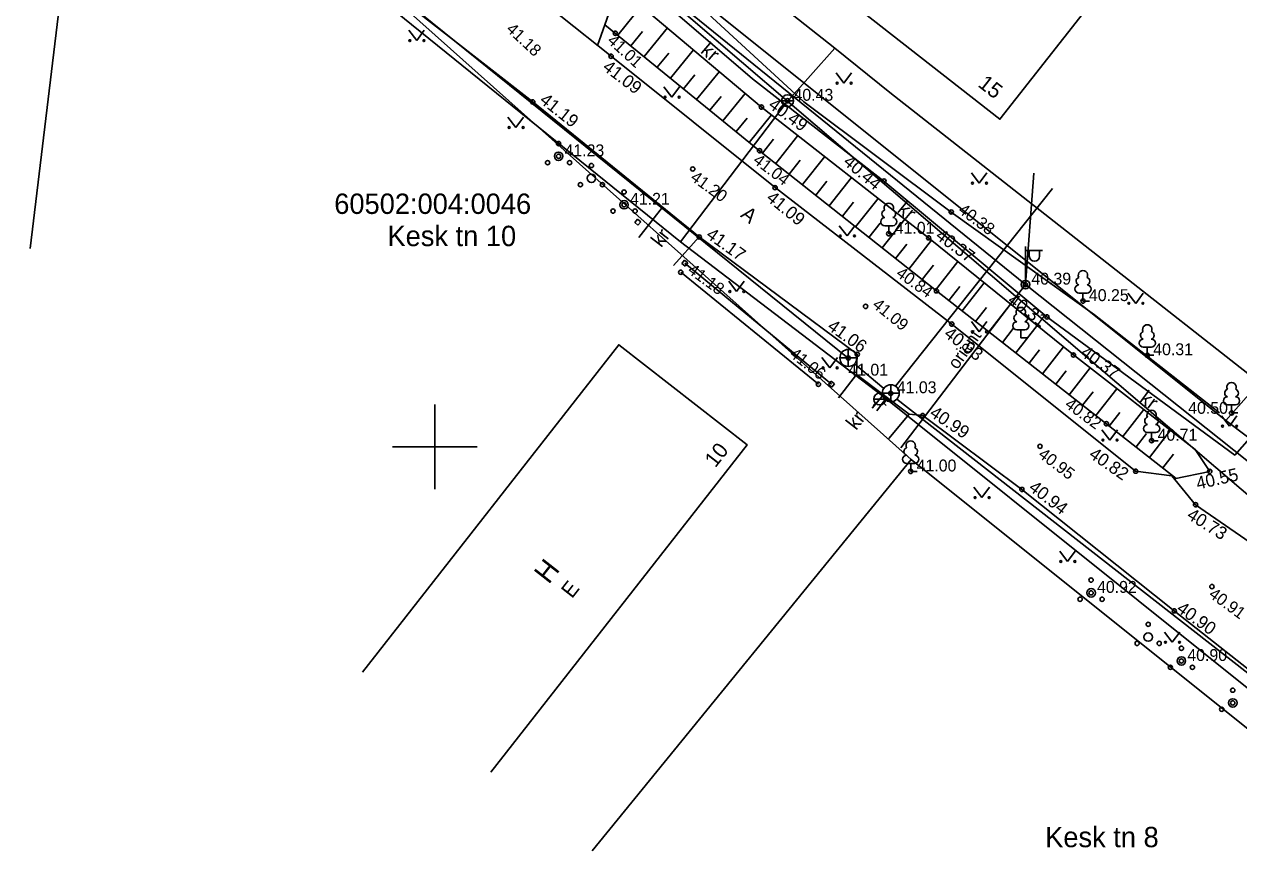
# Model space of a CAD drawing. Extents: x 641898 to 642452, y 6471715 to 6472255.
# Drawn here: x 642175.8 to 642247.4, y 6471876 to 6471924.9 of the extents above; entities that cross this region are included whole.
import ezdxf

# ---------------------------------------------------------------- set-up
doc = ezdxf.new("R2010")
doc.units = 0
for name, color, linetype in [('AED', 7, 'Continuous'), ('HALJASTUS', 7, 'Continuous'), ('HOONE', 7, 'Continuous'), ('KKAEV', 7, 'Continuous'), ('KORGUS-EH2000', 7, 'Continuous'), ('KTRASS', 7, 'Continuous'), ('MPOHULIIN', 7, 'Continuous'), ('PIIR', 7, 'Continuous'), ('POST', 7, 'Continuous'), ('PUU', 7, 'Continuous'), ('RELJEEF', 7, 'Continuous'), ('TEE', 7, 'Continuous'), ('VKAEV', 7, 'Continuous'), ('VORK', 7, 'Continuous'), ('VTRASS', 7, 'Continuous')]:
    doc.layers.add(name, color=color, linetype=linetype)

msp = doc.modelspace()

# ---------------------------------------------------------------- linework, layer by layer
at = {"layer": 'AED'}
for p, q in [((642211.941, 6471913.406), (642211.777, 6471913.218)), ((642211.777, 6471913.218), (642211.965, 6471913.054)), ((642211.941, 6471913.406), (642212.129, 6471913.242)), ((642212.129, 6471913.242), (642211.965, 6471913.054)), ((642214.702, 6471910.995), (642214.543, 6471910.802)), ((642214.543, 6471910.802), (642214.736, 6471910.643)), ((642214.702, 6471910.995), (642214.895, 6471910.836)), ((642214.719, 6471910.819), (642223.37, 6471903.693)), ((642214.895, 6471910.836), (642214.736, 6471910.643)), ((642223.194, 6471903.676), (642223.353, 6471903.869)), ((642223.546, 6471903.71), (642223.353, 6471903.869)), ((642223.387, 6471903.517), (642223.194, 6471903.676)), ((642223.387, 6471903.517), (642223.546, 6471903.71))]:
    msp.add_line(p, q, dxfattribs=at)
at = {"layer": 'HALJASTUS'}
for p, q in [((642198.464, 6471924.531), (642198.927, 6471923.924)), ((642198.927, 6471923.924), (642199.373, 6471924.531)), ((642223.635, 6471922.024), (642224.098, 6471921.417)), ((642224.098, 6471921.417), (642224.544, 6471922.024)), ((642213.497, 6471921.203), (642213.96, 6471920.596)), ((642213.96, 6471920.596), (642214.406, 6471921.203)), ((642204.307, 6471919.418), (642204.771, 6471918.811)), ((642204.771, 6471918.811), (642205.216, 6471919.418)), ((642231.607, 6471916.14), (642232.071, 6471915.533)), ((642232.071, 6471915.533), (642232.516, 6471916.14)), ((642223.826, 6471913.025), (642224.289, 6471912.419)), ((642224.289, 6471912.419), (642224.735, 6471913.025)), ((642217.316, 6471909.751), (642217.779, 6471909.145)), ((642217.779, 6471909.145), (642218.225, 6471909.751)), ((642240.828, 6471909.059), (642241.291, 6471908.452)), ((642241.291, 6471908.452), (642241.737, 6471909.059)), ((642231.607, 6471907.384), (642232.071, 6471906.777)), ((642232.071, 6471906.777), (642232.516, 6471907.384)), ((642222.807, 6471905.256), (642223.27, 6471904.649)), ((642223.27, 6471904.649), (642223.716, 6471905.256)), ((642246.348, 6471901.831), (642246.811, 6471901.224)), ((642246.811, 6471901.224), (642247.257, 6471901.831)), ((642239.301, 6471901.008), (642239.764, 6471900.402)), ((642239.764, 6471900.402), (642240.21, 6471901.008)), ((642231.763, 6471897.617), (642232.226, 6471897.01)), ((642232.226, 6471897.01), (642232.672, 6471897.617)), ((642236.814, 6471893.856), (642237.277, 6471893.249)), ((642237.277, 6471893.249), (642237.723, 6471893.856)), ((642242.98, 6471889.096), (642243.444, 6471888.489)), ((642243.444, 6471888.489), (642243.889, 6471889.096))]:
    msp.add_line(p, q, dxfattribs=at)
for points in [[(642212.922, 6471928.455), (642221.728, 6471920.311), (642230.423, 6471913.829), (642238.86, 6471907.776), (642246.219, 6471901.994)], [(642214.485, 6471910.283), (642222.598, 6471903.689)]]:
    msp.add_lwpolyline(points, dxfattribs=at)
for centre in [(642198.526, 6471923.924), (642199.355, 6471923.924), (642223.697, 6471921.417), (642224.526, 6471921.417), (642213.559, 6471920.596), (642214.388, 6471920.596), (642204.37, 6471918.811), (642205.198, 6471918.811), (642231.67, 6471915.533), (642232.498, 6471915.533), (642223.888, 6471912.419), (642224.717, 6471912.419), (642217.378, 6471909.145), (642218.207, 6471909.145), (642240.89, 6471908.452), (642241.719, 6471908.452), (642231.67, 6471906.777), (642232.498, 6471906.777), (642222.869, 6471904.649), (642223.698, 6471904.649), (642246.41, 6471901.224), (642247.239, 6471901.224), (642239.363, 6471900.402), (642240.192, 6471900.402), (642231.825, 6471897.01), (642232.654, 6471897.01), (642236.876, 6471893.249), (642237.705, 6471893.249), (642243.042, 6471888.489), (642243.871, 6471888.489)]:
    msp.add_circle(centre, 0.055, dxfattribs=at)
at = {"layer": 'HOONE'}
for points in [[(642240.821, 6471928.89), (642233.287, 6471919.295), (642217.105, 6471931.958), (642224.638, 6471941.553), (642240.821, 6471928.89)], [(642195.732, 6471886.734), (642210.829, 6471906.017), (642218.394, 6471900.125), (642203.303, 6471880.85)]]:
    msp.add_lwpolyline(points, dxfattribs=at)
at = {"layer": 'KKAEV'}
for p, q in [((642224.359, 6471904.734), (642224.359, 6471905.734)), ((642223.859, 6471905.234), (642224.859, 6471905.234)), ((642226.362, 6471903.159), (642227.362, 6471903.159)), ((642226.862, 6471902.659), (642226.862, 6471903.659))]:
    msp.add_line(p, q, dxfattribs=at)
for centre in [(642224.359, 6471905.234), (642226.862, 6471903.159)]:
    msp.add_circle(centre, 0.5, dxfattribs=at)
at = {"layer": 'KORGUS-EH2000'}
for centre in [(642210.631, 6471924.357), (642210.382, 6471923.001), (642205.766, 6471920.313), (642220.779, 6471920.383), (642219.24, 6471920.009), (642219.132, 6471917.438), (642207.287, 6471917.112), (642215.191, 6471916.365), (642220.045, 6471915.264), (642226.459, 6471915.651), (642211.146, 6471914.258), (642230.423, 6471913.829), (642215.573, 6471912.361), (642226.74, 6471912.55), (642229.091, 6471912.308), (642214.485, 6471910.283), (642234.793, 6471909.555), (642229.553, 6471909.186), (642225.374, 6471908.271), (642238.184, 6471908.585), (642236.062, 6471907.65), (642230.451, 6471907.231), (642224.359, 6471905.234), (642224.883, 6471905.449), (642237.623, 6471905.411), (642241.974, 6471905.397), (642222.598, 6471903.689), (642226.862, 6471903.159), (642228.739, 6471901.846), (642246.936, 6471901.997), (642239.564, 6471901.36), (642242.228, 6471900.362), (642235.652, 6471900.03), (642228.033, 6471898.552), (642241.287, 6471898.567), (642245.655, 6471898.552), (642234.582, 6471897.491), (642244.819, 6471896.591), (642245.779, 6471891.77), (642238.662, 6471891.402), (642243.566, 6471890.342), (642243.982, 6471887.389), (642247.009, 6471884.919)]:
    msp.add_circle(centre, 0.125, dxfattribs=at)
at = {"layer": 'KTRASS'}
for points in [[(642155.58, 6471980.633), (642150.419, 6471974.152), (642145.759, 6471968.585), (642185.052, 6471936.9), (642224.346, 6471905.214)], [(642227.137, 6471903.577), (642236.381, 6471915.22)], [(642226.446, 6471903.437), (642224.725, 6471904.893)], [(642226.032, 6471902.121), (642226.528, 6471902.787)], [(642255.424, 6471880.798), (642227.22, 6471902.81)]]:
    msp.add_lwpolyline(points, dxfattribs=at)
at = {"layer": 'MPOHULIIN'}
for points in [[(642355.522, 6471813.313), (642331.534, 6471832.393), (642302.222, 6471855.921), (642271.629, 6471880.301), (642234.793, 6471909.555), (642198.436, 6471939.015), (642169.975, 6471961.956), (642133.076, 6471995.171), (642102.99, 6472021.089), (642074.552, 6472045.947), (642044.597, 6472041.824), (642019.939, 6472060.923), (641980.015, 6472091.706), (641945.513, 6472065.466), (641932.178, 6472056.628)], [(642235.289, 6471916.123), (642234.793, 6471909.555)], [(642227.443, 6471899.938), (642234.793, 6471909.555)]]:
    msp.add_lwpolyline(points, dxfattribs=at)
at = {"layer": 'PIIR'}
for p, q in [((642246.6, 6471901.55), (642186.7, 6471949.52)), ((642186.7, 6471949.52), (642250.92, 6471894.58)), ((642176.155, 6471911.686), (642179.85, 6471942.23)), ((642179.85, 6471942.23), (642228.06, 6471899.25)), ((642262.52, 6471919.68), (642246.6, 6471901.55)), ((642246.6, 6471901.55), (642252.4, 6471897.15)), ((642209.264, 6471876.218), (642228.06, 6471899.25)), ((642228.06, 6471899.25), (642288.16, 6471851.19))]:
    msp.add_line(p, q, dxfattribs=at)
at = {"layer": 'POST'}
for p, q in [((642234.793, 6471909.805), (642234.793, 6471911.805)), ((642234.793, 6471911.555), (642235.793, 6471911.555)), ((642235.02, 6471911.234), (642235.02, 6471911.555)), ((642235.632, 6471911.234), (642235.632, 6471911.555))]:
    msp.add_line(p, q, dxfattribs=at)
msp.add_circle((642234.793, 6471909.555), 0.25, dxfattribs=at)
msp.add_arc((642235.326, 6471911.234), 0.306, 180, 0, dxfattribs=at)
at = {"layer": 'PUU'}
for p, q in [((642226.98, 6471913.025), (642226.5, 6471913.025)), ((642226.74, 6471912.55), (642226.74, 6471913.025)), ((642227.12, 6471912.55), (642226.74, 6471912.55)), ((642238.424, 6471909.06), (642237.944, 6471909.06)), ((642238.184, 6471908.585), (642238.184, 6471909.06)), ((642238.564, 6471908.585), (642238.184, 6471908.585)), ((642234.76, 6471906.891), (642234.28, 6471906.891)), ((642234.52, 6471906.416), (642234.52, 6471906.891)), ((642234.9, 6471906.416), (642234.52, 6471906.416)), ((642242.214, 6471905.872), (642241.734, 6471905.872)), ((642241.974, 6471905.397), (642241.974, 6471905.872)), ((642242.354, 6471905.397), (642241.974, 6471905.397)), ((642247.176, 6471902.472), (642246.696, 6471902.472)), ((642246.936, 6471901.997), (642246.936, 6471902.472)), ((642247.316, 6471901.997), (642246.936, 6471901.997)), ((642242.468, 6471900.837), (642241.988, 6471900.837)), ((642242.228, 6471900.362), (642242.228, 6471900.837)), ((642242.608, 6471900.362), (642242.228, 6471900.362)), ((642228.273, 6471899.027), (642227.793, 6471899.027)), ((642228.033, 6471898.552), (642228.033, 6471899.027)), ((642228.413, 6471898.552), (642228.033, 6471898.552))]:
    msp.add_line(p, q, dxfattribs=at)
for centre, radius in [((642207.287, 6471917.862), 0.125), ((642206.637, 6471916.737), 0.125), ((642207.287, 6471917.112), 0.25), ((642207.937, 6471916.737), 0.125), ((642209.222, 6471915.818), 0.25), ((642209.222, 6471916.568), 0.125), ((642208.572, 6471915.443), 0.125), ((642209.872, 6471915.443), 0.125), ((642211.146, 6471915.008), 0.125), ((642210.496, 6471913.883), 0.125), ((642211.146, 6471914.258), 0.25), ((642211.796, 6471913.883), 0.125), ((642238.662, 6471892.152), 0.125), ((642238.012, 6471891.027), 0.125), ((642238.662, 6471891.402), 0.25), ((642239.312, 6471891.027), 0.125), ((642242.025, 6471889.547), 0.125), ((642242.025, 6471888.797), 0.25), ((642241.375, 6471888.422), 0.125), ((642242.675, 6471888.422), 0.125), ((642243.982, 6471888.139), 0.125), ((642243.982, 6471887.389), 0.25), ((642243.332, 6471887.014), 0.125), ((642244.632, 6471887.014), 0.125), ((642247.009, 6471885.669), 0.125), ((642246.359, 6471884.544), 0.125), ((642247.009, 6471884.919), 0.25)]:
    msp.add_circle(centre, radius, dxfattribs=at)
for centre, radius, start, end in [((642226.57, 6471913.723), 0.233, 109.02174, 253.14154), ((642226.74, 6471914.07), 0.277, 332.5799, 207.4201), ((642226.91, 6471913.723), 0.233, 286.85082, 70.98591), ((642226.503, 6471913.262), 0.238, 90.0016, 269.3953), ((642226.977, 6471913.262), 0.238, 270.6047, 89.9984), ((642238.184, 6471910.105), 0.277, 332.5799, 207.4201), ((642238.014, 6471909.758), 0.233, 109.02174, 253.14154), ((642238.354, 6471909.758), 0.233, 286.85082, 70.98591), ((642237.947, 6471909.297), 0.238, 90.0016, 269.3953), ((642238.421, 6471909.297), 0.238, 270.6047, 89.9984), ((642234.52, 6471907.936), 0.277, 332.5799, 207.4201), ((642234.35, 6471907.589), 0.233, 109.02174, 253.14154), ((642234.69, 6471907.589), 0.233, 286.85082, 70.98591), ((642234.283, 6471907.128), 0.238, 90.0016, 269.3953), ((642234.757, 6471907.128), 0.238, 270.6047, 89.9984), ((642241.804, 6471906.57), 0.233, 109.02174, 253.14154), ((642241.974, 6471906.917), 0.277, 332.5799, 207.4201), ((642242.144, 6471906.57), 0.233, 286.85082, 70.98591), ((642241.737, 6471906.109), 0.238, 90.0016, 269.3953), ((642242.211, 6471906.109), 0.238, 270.6047, 89.9984), ((642246.766, 6471903.17), 0.233, 109.02174, 253.14154), ((642246.936, 6471903.517), 0.277, 332.5799, 207.4201), ((642247.106, 6471903.17), 0.233, 286.85082, 70.98591), ((642246.699, 6471902.709), 0.238, 90.0016, 269.3953), ((642247.173, 6471902.709), 0.238, 270.6047, 89.9984), ((642242.058, 6471901.535), 0.233, 109.02174, 253.14154), ((642242.228, 6471901.882), 0.277, 332.5799, 207.4201), ((642242.398, 6471901.535), 0.233, 286.85082, 70.98591), ((642241.991, 6471901.074), 0.238, 90.0016, 269.3953), ((642242.465, 6471901.074), 0.238, 270.6047, 89.9984), ((642228.033, 6471900.072), 0.277, 332.5799, 207.4201), ((642227.863, 6471899.725), 0.233, 109.02174, 253.14154), ((642228.203, 6471899.725), 0.233, 286.85082, 70.98591), ((642227.796, 6471899.264), 0.238, 90.0016, 269.3953), ((642228.27, 6471899.264), 0.238, 270.6047, 89.9984)]:
    msp.add_arc(centre, radius, start, end, dxfattribs=at)
at = {"layer": 'RELJEEF'}
for p, q in [((642210.769, 6471924.245), (642212.172, 6471925.968)), ((642212.32, 6471922.982), (642213.701, 6471924.679)), ((642212.241, 6471924.468), (642211.545, 6471923.613)), ((642213.781, 6471923.192), (642213.096, 6471922.351)), ((642213.872, 6471921.72), (642215.231, 6471923.389)), ((642215.321, 6471921.917), (642214.647, 6471921.088)), ((642215.423, 6471920.457), (642216.76, 6471922.1)), ((642216.861, 6471920.641), (642216.198, 6471919.826)), ((642216.974, 6471919.195), (642218.289, 6471920.811)), ((642218.402, 6471919.365), (642217.749, 6471918.563)), ((642218.525, 6471917.932), (642219.834, 6471919.545)), ((642220.086, 6471916.682), (642221.39, 6471918.328)), ((642219.957, 6471918.12), (642219.302, 6471917.303)), ((642221.524, 6471916.887), (642220.87, 6471916.061)), ((642221.654, 6471915.441), (642222.966, 6471917.097)), ((642223.096, 6471915.65), (642222.438, 6471914.82)), ((642223.222, 6471914.199), (642224.541, 6471915.865)), ((642224.79, 6471912.957), (642226.117, 6471914.633)), ((642224.668, 6471914.414), (642224.006, 6471913.578)), ((642226.239, 6471913.177), (642225.574, 6471912.337)), ((642226.358, 6471911.716), (642227.693, 6471913.401)), ((642227.811, 6471911.94), (642227.142, 6471911.095)), ((642227.926, 6471910.474), (642229.266, 6471912.166)), ((642229.377, 6471910.696), (642228.71, 6471909.853)), ((642229.494, 6471909.233), (642230.817, 6471910.913)), ((642231.069, 6471908.001), (642232.367, 6471909.66)), ((642230.935, 6471909.452), (642230.282, 6471908.616)), ((642232.501, 6471908.208), (642231.857, 6471907.385)), ((642232.645, 6471906.769), (642233.922, 6471908.403)), ((642234.066, 6471906.963), (642233.433, 6471906.153)), ((642234.221, 6471905.537), (642235.478, 6471907.145)), ((642235.632, 6471905.719), (642235.009, 6471904.921)), ((642235.796, 6471904.305), (642237.033, 6471905.888)), ((642237.372, 6471903.073), (642238.605, 6471904.651)), ((642237.199, 6471904.476), (642236.584, 6471903.689)), ((642238.778, 6471903.248), (642238.16, 6471902.458)), ((642238.948, 6471901.842), (642240.187, 6471903.426)), ((642240.357, 6471902.02), (642239.736, 6471901.226)), ((642240.523, 6471900.61), (642241.768, 6471902.202)), ((642241.935, 6471900.792), (642241.311, 6471899.994)), ((642242.099, 6471899.378), (642243.35, 6471900.978)), ((642243.514, 6471899.564), (642242.887, 6471898.762))]:
    msp.add_line(p, q, dxfattribs=at)
msp.add_lwpolyline([(642210.016, 6471924.858), (642219.132, 6471917.438), (642229.553, 6471909.186), (642243.675, 6471898.146)], dxfattribs=at)
at = {"layer": 'TEE'}
for p, q in [((642213.401, 6471914.122), (642212.009, 6471912.326)), ((642215.573, 6471912.361), (642214.062, 6471910.678)), ((642224.85, 6471904.256), (642223.778, 6471902.88)), ((642227.951, 6471901.93), (642226.75, 6471900.494))]:
    msp.add_line(p, q, dxfattribs=at)
for points in [[(642248.038, 6471894.359), (642244.819, 6471896.591), (642243.421, 6471898.287), (642241.287, 6471898.567), (642230.451, 6471907.231), (642220.045, 6471915.264), (642210.382, 6471923.001), (642201.484, 6471930.096), (642191.341, 6471938.065), (642180.941, 6471946.534), (642171.256, 6471954.365), (642153.477, 6471969.856), (642154.958, 6471971.99), (642153.566, 6471973.386), (642153.495, 6471974.667), (642149.137, 6471978.135), (642148.146, 6471977.701), (642140.89, 6471983.962), (642132.244, 6471991.056), (642124.462, 6471997.136), (642114.29, 6472005.762), (642111.738, 6472008.121), (642108.086, 6472011.066)], [(642253.944, 6471882.162), (642243.566, 6471890.342), (642234.582, 6471897.491), (642228.739, 6471901.846), (642227.951, 6471901.93), (642224.85, 6471904.256), (642224.883, 6471905.449), (642215.573, 6471912.361), (642205.766, 6471920.313), (642195.477, 6471928.355), (642185.674, 6471936.257), (642176.022, 6471944.175), (642167.777, 6471951.014), (642158.111, 6471959.24), (642148.973, 6471966.102), (642138.436, 6471974.464), (642128.627, 6471982.536), (642127.755, 6471983.25), (642118.56, 6471990.787)], [(642250.614, 6471903.45), (642247.126, 6471899.514), (642236.062, 6471907.65), (642226.459, 6471915.651), (642218.711, 6471921.682), (642211.545, 6471927.832), (642211.763, 6471928.205), (642212.454, 6471929.13), (642215.961, 6471933.863)], [(642243.557, 6471898.122), (642245.655, 6471898.552), (642244.803, 6471899.853), (642237.623, 6471905.411), (642229.091, 6471912.308), (642219.24, 6471920.009), (642211.023, 6471926.937), (642210.355, 6471925.793), (642209.576, 6471923.644)]]:
    msp.add_lwpolyline(points, dxfattribs=at)
at = {"layer": 'VKAEV'}
for p, q in [((642220.429, 6471920.383), (642221.129, 6471920.383)), ((642220.532, 6471920.136), (642220.392, 6471919.996)), ((642221.026, 6471920.136), (642221.166, 6471919.996)), ((642225.962, 6471902.57), (642225.822, 6471902.43)), ((642225.859, 6471902.817), (642226.559, 6471902.817)), ((642226.456, 6471902.57), (642226.596, 6471902.43))]:
    msp.add_line(p, q, dxfattribs=at)
for centre in [(642220.779, 6471920.383), (642226.209, 6471902.817)]:
    msp.add_circle(centre, 0.35, dxfattribs=at)
at = {"layer": 'VORK'}
for p, q in [((642200, 6471902.5), (642200, 6471897.5)), ((642197.5, 6471900), (642202.5, 6471900))]:
    msp.add_line(p, q, dxfattribs=at)
at = {"layer": 'VTRASS'}
for points in [[(642256.057, 6471879.253), (642241.436, 6471890.95), (642226.363, 6471903.005), (642214.466, 6471912.082), (642191.253, 6471930.836), (642159.201, 6471956.73), (642153.648, 6471961.39), (642148.095, 6471966.051), (642145.394, 6471966.921), (642144.516, 6471967.495), (642143.631, 6471968.002), (642136.85, 6471974.118), (642135.798, 6471974.98), (642131.146, 6471978.791)], [(642261.241, 6471893.85), (642226.798, 6471920.874), (642223.555, 6471923.471), (642220.019, 6471926.258), (642175.39, 6471960.391)], [(642214.466, 6471912.082), (642220.689, 6471920.251), (642223.555, 6471923.471)], [(642225.769, 6471902.28), (642226.363, 6471903.005)]]:
    msp.add_lwpolyline(points, dxfattribs=at)

# ---------------------------------------------------------------- texts
at = {"layer": 'HOONE'}
for s, height, rotation, p in [('15', 0.9, 321.955, (642231.939, 6471921.265)), ('10', 0.9, 51.94206, (642216.525, 6471898.731)), ('H', 1.2, 51.94206, (642206.703, 6471891.862)), ('E', 0.9, 51.94206, (642208.075, 6471891.026))]:
    msp.add_text(s, height=height, rotation=rotation, dxfattribs=at).set_placement(p)
at = {"layer": 'KORGUS-EH2000'}
for s, height, rotation, p in [('41.18', 0.7, 317.12373, (642204.153, 6471924.533)), ('41.01', 0.7, 317.6641, (642210.108, 6471923.849)), ('41.09', 0.75, 322.69699, (642209.826, 6471922.245)), ('41.19', 0.75, 321.6542, (642206.116, 6471920.313)), ('40.49', 0.75, 323.98841, (642219.59, 6471920.009)), ('41.04', 0.7, 322.59322, (642218.693, 6471916.766)), ('40.44', 0.75, 319.5831, (642224.007, 6471916.692)), ('41.20', 0.7, 324.06371, (642215.004, 6471915.744)), ('41.09', 0.75, 320.88929, (642219.472, 6471914.559)), ('40.38', 0.7, 323.3274, (642230.773, 6471913.829)), ('41.17', 0.75, 324.35579, (642215.923, 6471912.361)), ('40.37', 0.75, 323.11357, (642229.441, 6471912.308)), ('41.18', 0.7, 323.89261, (642214.835, 6471910.283)), ('40.84', 0.7, 324.48592, (642227.118, 6471910.092)), ('40.31', 0.75, 323.75632, (642233.694, 6471908.506)), ('41.09', 0.7, 320.7377, (642225.724, 6471908.271)), ('41.06', 0.75, 324.44604, (642223.068, 6471906.96)), ('40.93', 0.75, 322.67012, (642229.938, 6471906.54)), ('41.06', 0.7, 321.80442, (642220.843, 6471905.358)), ('40.37', 0.75, 324.09347, (642237.973, 6471905.411)), ('40.82', 0.7, 323.54242, (642237.061, 6471902.384)), ('40.99', 0.75, 325.97269, (642229.089, 6471901.846)), ('40.95', 0.7, 322.57803, (642235.495, 6471899.447)), ('40.82', 0.75, 325.20604, (642238.479, 6471899.418)), ('40.55', 0.75, 12.93045, (642244.948, 6471897.477)), ('40.94', 0.75, 322.36593, (642234.932, 6471897.491)), ('40.73', 0.75, 327.78874, (642244.246, 6471895.819)), ('40.91', 0.7, 323.85689, (642245.542, 6471891.199)), ('40.90', 0.75, 324.37917, (642243.643, 6471890.342))]:
    msp.add_text(s, height=height, rotation=rotation, dxfattribs=at).set_placement(p)
for s, p in [('40.43', (642221.129, 6471920.383)), ('41.23', (642207.637, 6471917.112)), ('41.21', (642211.496, 6471914.258)), ('41.01', (642227.09, 6471912.55)), ('40.39', (642235.143, 6471909.555)), ('40.25', (642238.534, 6471908.585)), ('40.31', (642242.324, 6471905.397)), ('41.01', (642224.357, 6471904.193)), ('41.03', (642227.212, 6471903.159)), ('40.50', (642244.383, 6471901.947)), ('40.71', (642242.578, 6471900.362)), ('41.00', (642228.383, 6471898.552)), ('40.92', (642239.012, 6471891.402)), ('40.90', (642244.332, 6471887.389))]:
    msp.add_text(s, height=0.7, dxfattribs=at).set_placement(p)
at = {"layer": 'MPOHULIIN'}
msp.add_text('orient', height=0.75, rotation=54.47794, dxfattribs=at).set_placement((642230.776, 6471904.512))
at = {"layer": 'PIIR'}
for s, p in [('60502:004:0046', (642194.07, 6471913.717)), ('Kesk tn 10', (642197.206, 6471911.821)), ('Kesk tn 8', (642235.956, 6471876.422))]:
    msp.add_text(s, height=1.2, dxfattribs=at).set_placement(p)
at = {"layer": 'TEE'}
for s, rotation, p in [('kr', 319.36043, (642215.6, 6471923.251)), ('A', 321.31634, (642217.958, 6471913.581)), ('kr', 320.19971, (642227.191, 6471913.882)), ('kr', 52.23937, (642213.331, 6471911.695)), ('kr', 323.6684, (642241.455, 6471902.698)), ('kr', 52.07518, (642224.821, 6471900.929))]:
    msp.add_text(s, height=0.85, rotation=rotation, dxfattribs=at).set_placement(p)

doc.saveas('drawing.dxf')
